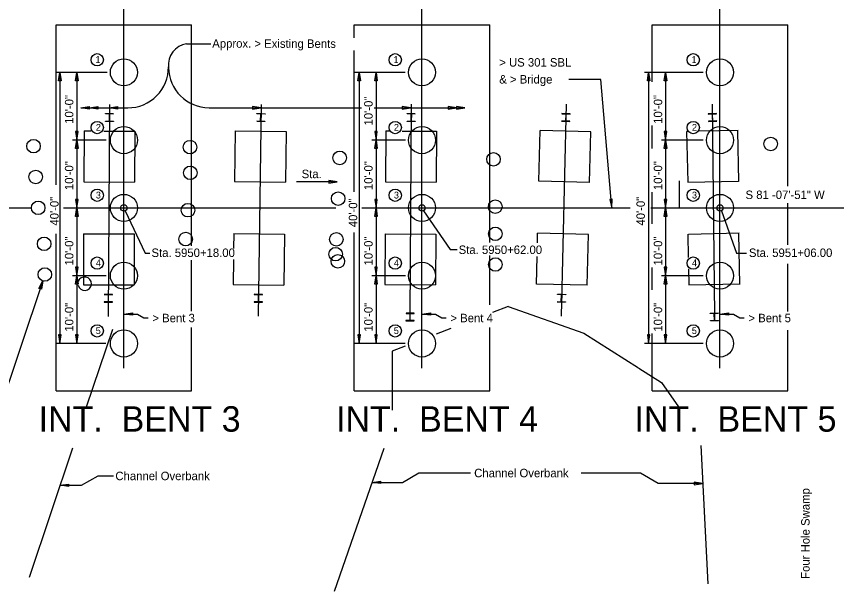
# Model space of a CAD drawing. Extents: x -10371 to -10009, y 1939 to 2167.
# Drawn here: x -10258.8 to -10137.7, y 2027.9 to 2112.7 of the extents above; entities that cross this region are included whole.
import ezdxf

# ---------------------------------------------------------------- set-up
doc = ezdxf.new("R2010")
doc.units = 0
for name, color, linetype in [('BR_AUTO DIMENSION', 7, 'Continuous'), ('BR_CENTER LINES', 7, 'Continuous'), ('BR_CONCRETE', 7, 'Continuous'), ('BR_STRUCTURAL STEEL', 7, 'Continuous'), ('BR_TABLE LINES', 7, 'Continuous'), ('BR_TEXT', 7, 'Continuous'), ('Default', 7, 'Continuous')]:
    doc.layers.add(name, color=color, linetype=linetype)

msp = doc.modelspace()

# ---------------------------------------------------------------- linework, layer by layer
at = {"layer": 'BR_AUTO DIMENSION'}
for p, q in [((-10233.68, 2108.7), (-10230.06, 2108.7)), ((-10245.4, 2104.49), (-10252.99, 2104.49)), ((-10252.37, 2104.49), (-10252.37, 2064.49)), ((-10249.87, 2104.49), (-10249.87, 2064.49)), ((-10249.69, 2104.49), (-10249.69, 2104.49)), ((-10201.4, 2104.49), (-10208.81, 2104.49)), ((-10208.19, 2104.49), (-10208.19, 2064.49)), ((-10205.69, 2104.49), (-10205.69, 2104.49)), ((-10205.69, 2104.49), (-10205.69, 2064.49)), ((-10157.4, 2104.49), (-10166.06, 2104.49)), ((-10165.44, 2104.49), (-10165.44, 2064.49)), ((-10162.94, 2104.49), (-10162.94, 2104.49)), ((-10162.94, 2104.49), (-10162.94, 2064.49)), ((-10172.48, 2103.43), (-10177.22, 2103.43)), ((-10170.87, 2084.49), (-10172.48, 2103.43)), ((-10249.27, 2099.26), (-10242.33, 2099.26)), ((-10230.33, 2099.26), (-10207.82, 2099.26)), ((-10205.95, 2099.26), (-10192.56, 2099.26)), ((-10245.54, 2094.49), (-10250.49, 2094.49)), ((-10201.36, 2094.49), (-10206.31, 2094.49)), ((-10157.4, 2094.49), (-10163.56, 2094.49)), ((-10211.43, 2088.32), (-10217.41, 2088.32)), ((-10242.7, 2084.07), (-10239.75, 2077.83)), ((-10198.7, 2084.07), (-10194.72, 2078.36)), ((-10154.7, 2084.07), (-10152.48, 2077.83)), ((-10239.75, 2077.83), (-10239.1, 2077.83)), ((-10194.72, 2078.36), (-10193.7, 2078.36)), ((-10152.48, 2077.83), (-10151.02, 2077.83)), ((-10245.54, 2074.49), (-10250.49, 2074.49)), ((-10201.36, 2074.49), (-10206.31, 2074.49)), ((-10157.4, 2074.49), (-10163.56, 2074.49)), ((-10254.89, 2073.72), (-10265.12, 2043.24)), ((-10242.91, 2068.83), (-10240.91, 2068.83)), ((-10240.91, 2068.83), (-10239.97, 2068.29)), ((-10239.97, 2068.29), (-10239.32, 2068.29)), ((-10198.91, 2068.83), (-10196.91, 2068.83)), ((-10196.91, 2068.83), (-10195.97, 2068.29)), ((-10195.97, 2068.29), (-10195.32, 2068.29)), ((-10154.91, 2068.83), (-10152.91, 2068.83)), ((-10152.91, 2068.83), (-10151.97, 2068.29)), ((-10151.97, 2068.29), (-10151.32, 2068.29)), ((-10245.58, 2064.49), (-10252.99, 2064.49)), ((-10249.87, 2064.49), (-10249.87, 2064.49)), ((-10201.4, 2064.49), (-10208.81, 2064.49)), ((-10205.69, 2064.49), (-10205.69, 2064.49)), ((-10157.4, 2064.49), (-10166.06, 2064.49)), ((-10162.94, 2064.49), (-10162.94, 2064.49)), ((-10201.76, 2043.99), (-10199.35, 2045.39)), ((-10199.35, 2045.39), (-10191.72, 2045.39)), ((-10166.66, 2045.35), (-10175.41, 2045.35)), ((-10164.05, 2043.84), (-10166.66, 2045.35)), ((-10249.15, 2043.56), (-10246.73, 2044.95)), ((-10246.73, 2044.95), (-10244.46, 2044.95)), ((-10206.27, 2043.99), (-10201.76, 2043.99)), ((-10252.34, 2043.56), (-10249.15, 2043.56)), ((-10157.46, 2043.84), (-10164.05, 2043.84))]:
    msp.add_line(p, q, dxfattribs=at)
for points in [[(-10252.56, 2103.24), (-10252.37, 2104.49), (-10252.18, 2103.24)], [(-10250.06, 2103.24), (-10249.87, 2104.49), (-10249.68, 2103.24)], [(-10208.38, 2103.24), (-10208.19, 2104.49), (-10208, 2103.24)], [(-10205.88, 2103.24), (-10205.69, 2104.49), (-10205.5, 2103.24)], [(-10165.63, 2103.24), (-10165.44, 2104.49), (-10165.25, 2103.24)], [(-10163.13, 2103.24), (-10162.94, 2104.49), (-10162.75, 2103.24)], [(-10248.02, 2099.08), (-10249.27, 2099.26), (-10248.02, 2099.45)], [(-10246.77, 2099.08), (-10248.02, 2099.26), (-10246.77, 2099.45)], [(-10243.86, 2099.08), (-10245.11, 2099.26), (-10243.86, 2099.45)], [(-10223.92, 2099.08), (-10222.67, 2099.26), (-10223.92, 2099.45)], [(-10201.81, 2099.08), (-10200.56, 2099.26), (-10201.81, 2099.45)], [(-10195.06, 2099.08), (-10193.81, 2099.26), (-10195.06, 2099.45)], [(-10193.81, 2099.08), (-10192.56, 2099.26), (-10193.81, 2099.45)], [(-10250.06, 2095.74), (-10249.87, 2094.49), (-10249.68, 2095.74)], [(-10205.88, 2095.74), (-10205.69, 2094.49), (-10205.5, 2095.74)], [(-10163.13, 2095.74), (-10162.94, 2094.49), (-10162.75, 2095.74)], [(-10250.06, 2093.24), (-10249.87, 2094.49), (-10249.68, 2093.24)], [(-10205.88, 2093.24), (-10205.69, 2094.49), (-10205.5, 2093.24)], [(-10163.13, 2093.24), (-10162.94, 2094.49), (-10162.75, 2093.24)], [(-10212.68, 2088.13), (-10211.43, 2088.32), (-10212.68, 2088.51)], [(-10250.06, 2085.74), (-10249.87, 2084.49), (-10249.68, 2085.74)], [(-10205.88, 2085.74), (-10205.69, 2084.49), (-10205.5, 2085.74)], [(-10171.18, 2085.72), (-10170.87, 2084.49), (-10170.81, 2085.76)], [(-10163.13, 2085.74), (-10162.94, 2084.49), (-10162.75, 2085.74)], [(-10250.06, 2083.24), (-10249.87, 2084.49), (-10249.68, 2083.24)], [(-10205.88, 2083.24), (-10205.69, 2084.49), (-10205.5, 2083.24)], [(-10163.13, 2083.24), (-10162.94, 2084.49), (-10162.75, 2083.24)], [(-10250.06, 2075.74), (-10249.87, 2074.49), (-10249.68, 2075.74)], [(-10205.88, 2075.74), (-10205.69, 2074.49), (-10205.5, 2075.74)], [(-10163.13, 2075.74), (-10162.94, 2074.49), (-10162.75, 2075.74)], [(-10250.06, 2073.24), (-10249.87, 2074.49), (-10249.68, 2073.24)], [(-10205.88, 2073.24), (-10205.69, 2074.49), (-10205.5, 2073.24)], [(-10163.13, 2073.24), (-10162.94, 2074.49), (-10162.75, 2073.24)], [(-10255.46, 2072.59), (-10254.89, 2073.72), (-10255.1, 2072.48)], [(-10241.66, 2068.65), (-10242.91, 2068.83), (-10241.66, 2069.02)], [(-10197.66, 2068.65), (-10198.91, 2068.83), (-10197.66, 2069.02)], [(-10153.66, 2068.65), (-10154.91, 2068.83), (-10153.66, 2069.02)], [(-10252.56, 2065.74), (-10252.37, 2064.49), (-10252.18, 2065.74)], [(-10250.06, 2065.74), (-10249.87, 2064.49), (-10249.68, 2065.74)], [(-10208.38, 2065.74), (-10208.19, 2064.49), (-10208, 2065.74)], [(-10205.88, 2065.74), (-10205.69, 2064.49), (-10205.5, 2065.74)], [(-10165.63, 2065.74), (-10165.44, 2064.49), (-10165.25, 2065.74)], [(-10163.13, 2065.74), (-10162.94, 2064.49), (-10162.75, 2065.74)], [(-10205.02, 2043.81), (-10206.27, 2043.99), (-10205.02, 2044.18)], [(-10158.71, 2043.65), (-10157.46, 2043.84), (-10158.71, 2044.03)], [(-10251.09, 2043.37), (-10252.34, 2043.56), (-10251.09, 2043.74)]]:
    msp.add_lwpolyline(points, close=True, dxfattribs=at)
for centre in [(-10242.91, 2084.49), (-10198.91, 2084.49), (-10154.91, 2084.49)]:
    msp.add_circle(centre, 0.469, dxfattribs=at)
for centre, radius, start, end in [((-10233.19, 2105.58), 3.16, 98.8893, 186.288), ((-10242.33, 2105.26), 6, 270, 0.323), ((-10230.33, 2105.26), 6, 180.323, 270)]:
    msp.add_arc(centre, radius, start, end, dxfattribs=at)
at = {"layer": 'BR_CENTER LINES'}
for p, q in [((-10242.91, 2060.87), (-10242.91, 2124.66)), ((-10198.91, 2060.87), (-10198.91, 2124.66)), ((-10154.91, 2060.87), (-10154.91, 2124.66)), ((-10160.91, 2084.49), (-10160.91, 2088.49)), ((-10267.37, 2084.49), (-10256.58, 2084.49)), ((-10251.83, 2084.49), (-10211.63, 2084.49)), ((-10207.77, 2084.49), (-10168.15, 2084.49)), ((-10165.1, 2084.49), (-10123.98, 2084.49))]:
    msp.add_line(p, q, dxfattribs=at)
at = {"layer": 'BR_CONCRETE'}
for p, q in [((-10248.8, 2095.85), (-10248.85, 2088.35)), ((-10248.8, 2095.85), (-10247.8, 2095.84)), ((-10245.86, 2095.83), (-10241.3, 2095.8)), ((-10241.3, 2095.8), (-10241.35, 2088.3)), ((-10226.47, 2095.88), (-10226.57, 2088.38)), ((-10226.47, 2095.88), (-10218.97, 2095.77)), ((-10218.97, 2095.77), (-10219.07, 2088.27)), ((-10204.26, 2095.85), (-10204.31, 2088.35)), ((-10204.26, 2095.85), (-10203.77, 2095.85)), ((-10201.84, 2095.83), (-10196.76, 2095.8)), ((-10196.76, 2095.8), (-10196.81, 2088.3)), ((-10181.65, 2088.42), (-10181.46, 2095.91)), ((-10173.97, 2095.73), (-10181.46, 2095.91)), ((-10174.15, 2088.23), (-10173.97, 2095.73)), ((-10159.62, 2095.75), (-10159.79, 2095.74)), ((-10159.63, 2088.29), (-10159.79, 2095.74)), ((-10152.25, 2095.91), (-10157.93, 2095.79)), ((-10152.13, 2088.37), (-10152.3, 2095.87)), ((-10248.85, 2088.35), (-10241.35, 2088.3)), ((-10226.57, 2088.38), (-10219.07, 2088.27)), ((-10204.31, 2088.35), (-10196.81, 2088.3)), ((-10174.15, 2088.23), (-10181.65, 2088.42)), ((-10152.17, 2088.41), (-10159.67, 2088.24)), ((-10248.88, 2080.66), (-10241.38, 2080.66)), ((-10248.88, 2080.66), (-10248.88, 2073.16)), ((-10241.38, 2080.66), (-10241.38, 2073.16)), ((-10226.68, 2080.71), (-10226.71, 2078.5)), ((-10226.68, 2080.71), (-10219.18, 2080.61)), ((-10219.18, 2080.61), (-10219.28, 2073.11)), ((-10204.35, 2080.68), (-10204.4, 2073.18)), ((-10204.35, 2080.68), (-10196.85, 2080.64)), ((-10196.85, 2080.64), (-10196.9, 2073.14)), ((-10181.87, 2079.32), (-10181.83, 2080.75)), ((-10174.33, 2080.57), (-10181.83, 2080.75)), ((-10174.52, 2073.07), (-10174.33, 2080.57)), ((-10159.55, 2077.15), (-10159.63, 2080.62)), ((-10152.09, 2080.75), (-10159.58, 2080.58)), ((-10151.96, 2073.2), (-10152.13, 2080.7)), ((-10226.73, 2076.86), (-10226.78, 2073.21)), ((-10182.01, 2073.25), (-10181.91, 2077.32)), ((-10159.46, 2073.12), (-10159.51, 2075.48)), ((-10248.88, 2073.16), (-10241.38, 2073.16)), ((-10226.78, 2073.21), (-10219.28, 2073.11)), ((-10204.4, 2073.18), (-10196.9, 2073.14)), ((-10174.52, 2073.07), (-10182.01, 2073.25)), ((-10152, 2073.25), (-10159.5, 2073.08))]:
    msp.add_line(p, q, dxfattribs=at)
for centre in [(-10242.91, 2104.49), (-10198.91, 2104.49), (-10154.91, 2104.49), (-10242.91, 2094.49), (-10198.91, 2094.49), (-10154.91, 2094.49), (-10242.91, 2084.49), (-10198.91, 2084.49), (-10154.91, 2084.49), (-10242.91, 2074.49), (-10198.91, 2074.49), (-10154.91, 2074.49), (-10242.91, 2064.49), (-10198.91, 2064.49), (-10154.91, 2064.49)]:
    msp.add_circle(centre, 2, dxfattribs=at)
at = {"layer": 'BR_STRUCTURAL STEEL'}
for p, q in [((-10223.29, 2098.36), (-10223.29, 2098.4)), ((-10223.29, 2098.4), (-10222.08, 2098.38)), ((-10177.04, 2098.38), (-10178.26, 2098.4)), ((-10178.26, 2098.4), (-10178.26, 2098.36)), ((-10155.43, 2098.41), (-10156.65, 2098.38)), ((-10155.43, 2098.37), (-10155.43, 2098.41)), ((-10245.65, 2097.26), (-10245.65, 2097.31)), ((-10245.65, 2097.31), (-10245.12, 2097.3)), ((-10244.44, 2097.26), (-10245.65, 2097.26)), ((-10245.64, 2098.36), (-10245.64, 2098.4)), ((-10245.64, 2098.4), (-10244.43, 2098.39)), ((-10245.11, 2098.35), (-10245.64, 2098.36)), ((-10245.06, 2097.36), (-10245.06, 2098.29)), ((-10245.02, 2098.29), (-10245.02, 2097.36)), ((-10244.97, 2097.3), (-10244.44, 2097.3)), ((-10244.43, 2098.35), (-10244.96, 2098.35)), ((-10244.44, 2097.3), (-10244.44, 2097.26)), ((-10244.43, 2098.39), (-10244.43, 2098.35)), ((-10223.31, 2097.27), (-10223.31, 2097.31)), ((-10223.31, 2097.31), (-10222.78, 2097.3)), ((-10222.09, 2097.25), (-10223.31, 2097.27)), ((-10222.76, 2098.35), (-10223.29, 2098.36)), ((-10222.72, 2097.36), (-10222.71, 2098.29)), ((-10222.66, 2098.29), (-10222.68, 2097.36)), ((-10222.62, 2097.3), (-10222.09, 2097.29)), ((-10222.08, 2098.34), (-10222.61, 2098.35)), ((-10222.09, 2097.29), (-10222.09, 2097.25)), ((-10222.08, 2098.38), (-10222.08, 2098.34)), ((-10201.11, 2097.26), (-10201.11, 2097.31)), ((-10201.11, 2097.31), (-10200.58, 2097.3)), ((-10199.89, 2097.26), (-10201.11, 2097.26)), ((-10201.1, 2098.36), (-10201.1, 2098.4)), ((-10201.1, 2098.4), (-10199.89, 2098.39)), ((-10200.57, 2098.35), (-10201.1, 2098.36)), ((-10200.52, 2097.36), (-10200.52, 2098.29)), ((-10200.47, 2098.29), (-10200.48, 2097.36)), ((-10199.89, 2098.35), (-10200.42, 2098.35)), ((-10200.42, 2097.3), (-10199.89, 2097.3)), ((-10199.89, 2098.39), (-10199.89, 2098.35)), ((-10199.89, 2097.3), (-10199.89, 2097.26)), ((-10177.76, 2097.3), (-10178.29, 2097.31)), ((-10178.29, 2097.31), (-10178.29, 2097.27)), ((-10178.29, 2097.27), (-10177.07, 2097.24)), ((-10178.26, 2098.36), (-10177.73, 2098.35)), ((-10177.68, 2098.29), (-10177.7, 2097.36)), ((-10177.66, 2097.35), (-10177.63, 2098.29)), ((-10177.07, 2097.28), (-10177.6, 2097.3)), ((-10177.58, 2098.35), (-10177.05, 2098.33)), ((-10177.07, 2097.24), (-10177.07, 2097.28)), ((-10177.05, 2098.33), (-10177.04, 2098.38)), ((-10156.65, 2098.38), (-10156.64, 2098.34)), ((-10156.64, 2098.34), (-10156.11, 2098.35)), ((-10156.09, 2097.3), (-10156.62, 2097.29)), ((-10156.62, 2097.29), (-10156.62, 2097.25)), ((-10156.62, 2097.25), (-10155.4, 2097.27)), ((-10156.06, 2098.3), (-10156.04, 2097.36)), ((-10155.99, 2097.36), (-10156.01, 2098.3)), ((-10155.96, 2098.35), (-10155.43, 2098.37)), ((-10155.41, 2097.32), (-10155.94, 2097.3)), ((-10155.4, 2097.27), (-10155.41, 2097.32)), ((-10245.3, 2070.64), (-10245.83, 2070.64)), ((-10245.83, 2070.64), (-10245.83, 2070.6)), ((-10245.83, 2070.6), (-10244.61, 2070.59)), ((-10244.6, 2071.72), (-10245.82, 2071.73)), ((-10245.82, 2071.73), (-10245.82, 2071.69)), ((-10245.82, 2071.69), (-10245.29, 2071.69)), ((-10245.23, 2071.63), (-10245.24, 2070.69)), ((-10245.2, 2070.69), (-10245.19, 2071.63)), ((-10244.61, 2070.63), (-10245.14, 2070.64)), ((-10245.13, 2071.69), (-10244.6, 2071.68)), ((-10244.61, 2070.59), (-10244.61, 2070.63)), ((-10244.6, 2071.68), (-10244.6, 2071.72)), ((-10223.15, 2070.64), (-10223.68, 2070.65)), ((-10223.68, 2070.65), (-10223.68, 2070.6)), ((-10223.68, 2070.6), (-10222.46, 2070.59)), ((-10222.45, 2071.72), (-10223.66, 2071.74)), ((-10223.66, 2071.74), (-10223.66, 2071.7)), ((-10223.66, 2071.7), (-10223.13, 2071.69)), ((-10223.08, 2071.63), (-10223.09, 2070.69)), ((-10223.05, 2070.69), (-10223.03, 2071.63)), ((-10222.46, 2070.63), (-10222.99, 2070.64)), ((-10222.98, 2071.69), (-10222.45, 2071.68)), ((-10222.46, 2070.59), (-10222.46, 2070.63)), ((-10222.45, 2071.68), (-10222.45, 2071.72)), ((-10178.93, 2070.61), (-10178.93, 2070.65)), ((-10178.93, 2070.65), (-10178.4, 2070.64)), ((-10177.72, 2070.58), (-10178.93, 2070.61)), ((-10178.91, 2071.7), (-10178.91, 2071.75)), ((-10178.91, 2071.75), (-10177.69, 2071.72)), ((-10178.38, 2071.69), (-10178.91, 2071.7)), ((-10178.35, 2070.7), (-10178.32, 2071.63)), ((-10178.28, 2071.63), (-10178.3, 2070.7)), ((-10178.25, 2070.64), (-10177.72, 2070.62)), ((-10177.69, 2071.67), (-10178.22, 2071.69)), ((-10177.72, 2070.62), (-10177.72, 2070.58)), ((-10177.69, 2071.72), (-10177.69, 2071.67)), ((-10200.05, 2068.96), (-10201.26, 2068.97)), ((-10201.26, 2068.97), (-10201.26, 2068.93)), ((-10201.26, 2068.93), (-10200.74, 2068.92)), ((-10200.68, 2068.87), (-10200.68, 2067.93)), ((-10200.64, 2067.93), (-10200.64, 2068.87)), ((-10200.58, 2068.92), (-10200.05, 2068.92)), ((-10200.05, 2068.92), (-10200.05, 2068.96)), ((-10156.35, 2068.95), (-10155.14, 2068.98)), ((-10156.35, 2068.91), (-10156.35, 2068.95)), ((-10155.82, 2068.92), (-10156.35, 2068.91)), ((-10155.74, 2067.93), (-10155.76, 2068.87)), ((-10155.72, 2068.87), (-10155.7, 2067.93)), ((-10155.13, 2068.94), (-10155.66, 2068.93)), ((-10155.14, 2068.98), (-10155.13, 2068.94)), ((-10200.74, 2067.87), (-10201.27, 2067.88)), ((-10201.27, 2067.88), (-10201.27, 2067.83)), ((-10201.27, 2067.83), (-10200.06, 2067.83)), ((-10200.06, 2067.87), (-10200.59, 2067.87)), ((-10200.06, 2067.83), (-10200.06, 2067.87)), ((-10156.33, 2067.86), (-10155.8, 2067.87)), ((-10156.32, 2067.82), (-10156.33, 2067.86)), ((-10155.11, 2067.85), (-10156.32, 2067.82)), ((-10155.64, 2067.88), (-10155.11, 2067.89)), ((-10155.11, 2067.89), (-10155.11, 2067.85))]:
    msp.add_line(p, q, dxfattribs=at)
for centre in [(-10147.42, 2093.93), (-10256.25, 2093.6), (-10233.15, 2093.46), (-10211.05, 2091.87), (-10188.35, 2091.66), (-10255.93, 2089.06), (-10233.11, 2089.67), (-10211.28, 2085.86), (-10255.56, 2084.5), (-10233.46, 2084.15), (-10188.09, 2084.67), (-10188.08, 2080.67), (-10233.79, 2079.89), (-10211.54, 2079.85), (-10254.69, 2079.19), (-10211.66, 2077.66), (-10211.32, 2076.61), (-10188.07, 2076.14), (-10254.58, 2074.67)]:
    msp.add_circle(centre, 1, dxfattribs=at)
for centre, radius, start, end in [((-10245.12, 2097.36), 0.0569, 269.6251, 359.6251), ((-10245.11, 2098.3), 0.0569, 359.6251, 89.6251), ((-10244.96, 2098.29), 0.0569, 89.6251, 179.6251), ((-10244.97, 2097.36), 0.0569, 179.6251, 269.6251), ((-10222.78, 2097.36), 0.0569, 269.2026, 359.2026), ((-10222.76, 2098.29), 0.0569, 359.2026, 89.2026), ((-10222.62, 2097.36), 0.0569, 179.2026, 269.2026), ((-10222.61, 2098.29), 0.0569, 89.2026, 179.2026), ((-10200.58, 2097.36), 0.0569, 269.6516, 359.6516), ((-10200.57, 2098.3), 0.0569, 359.6516, 89.6516), ((-10200.42, 2097.36), 0.0569, 179.6516, 269.6516), ((-10200.42, 2098.29), 0.0569, 89.6516, 179.6516), ((-10177.76, 2097.36), 0.0569, 268.6086, 358.6086), ((-10177.73, 2098.29), 0.0569, 358.6086, 88.6086), ((-10177.6, 2097.35), 0.0569, 178.6086, 268.6086), ((-10177.58, 2098.29), 0.0569, 88.6086, 178.6086), ((-10156.11, 2098.29), 0.0569, 1.2775, 91.2775), ((-10156.09, 2097.36), 0.0569, 271.2775, 1.2775), ((-10155.96, 2098.3), 0.0569, 91.2775, 181.2775), ((-10155.94, 2097.36), 0.0569, 181.2775, 271.2775), ((-10248.71, 2073.31), 1, 193.5328, 160.7088), ((-10245.3, 2070.69), 0.0569, 269.6251, 359.6251), ((-10245.29, 2071.63), 0.0569, 359.6251, 89.6251), ((-10245.14, 2070.69), 0.0569, 179.6251, 269.6251), ((-10245.13, 2071.63), 0.0569, 89.6251, 179.6251), ((-10223.15, 2070.69), 0.0569, 269.2026, 359.2026), ((-10223.13, 2071.63), 0.0569, 359.2026, 89.2026), ((-10222.99, 2070.69), 0.0569, 179.2026, 269.2026), ((-10222.98, 2071.63), 0.0569, 89.2026, 179.2026), ((-10178.4, 2070.7), 0.0569, 268.6086, 358.6086), ((-10178.38, 2071.63), 0.0569, 358.6086, 88.6086), ((-10178.25, 2070.69), 0.0569, 178.6086, 268.6086), ((-10178.22, 2071.63), 0.0569, 88.6086, 178.6086), ((-10200.74, 2068.87), 0.0569, 359.6516, 89.6516), ((-10200.58, 2068.86), 0.0569, 89.6516, 179.6516), ((-10155.82, 2068.87), 0.0569, 1.2775, 91.2775), ((-10155.66, 2068.87), 0.0569, 91.2775, 181.2775), ((-10200.74, 2067.93), 0.0569, 269.6516, 359.6516), ((-10200.59, 2067.93), 0.0569, 179.6516, 269.6516), ((-10155.8, 2067.93), 0.0569, 271.2775, 1.2775), ((-10155.64, 2067.93), 0.0569, 181.2775, 271.2775)]:
    msp.add_arc(centre, radius, start, end, dxfattribs=at)
at = {"layer": 'BR_TABLE LINES'}
for p, q in [((-10252.91, 2111.49), (-10232.91, 2111.49)), ((-10252.91, 2087.9), (-10252.91, 2111.49)), ((-10232.91, 2078.88), (-10232.91, 2111.49)), ((-10208.91, 2111.49), (-10188.91, 2111.49)), ((-10208.91, 2109.6), (-10208.91, 2111.49)), ((-10188.91, 2079.41), (-10188.91, 2111.49)), ((-10164.91, 2111.49), (-10144.91, 2111.49)), ((-10164.91, 2103.09), (-10164.91, 2111.49)), ((-10144.91, 2087.68), (-10144.91, 2111.49)), ((-10208.91, 2086.88), (-10208.91, 2107.71)), ((-10245.03, 2099.75), (-10245.23, 2068.49)), ((-10222.66, 2099.76), (-10223.1, 2068.51)), ((-10200.49, 2099.78), (-10200.68, 2068.52)), ((-10177.62, 2099.79), (-10178.38, 2068.54)), ((-10156.05, 2099.81), (-10155.7, 2068.56)), ((-10164.91, 2093.26), (-10164.91, 2096.64)), ((-10164.91, 2082.16), (-10164.91, 2086.81)), ((-10144.91, 2079.06), (-10144.91, 2085.21)), ((-10252.91, 2057.49), (-10252.91, 2080.66)), ((-10208.91, 2057.49), (-10208.91, 2080.85)), ((-10232.91, 2069.27), (-10232.91, 2076.78)), ((-10188.91, 2070.17), (-10188.91, 2077.46)), ((-10164.91, 2072.39), (-10164.91, 2075.71)), ((-10144.91, 2069.23), (-10144.91, 2076.22)), ((-10232.91, 2057.49), (-10232.91, 2066.86)), ((-10188.91, 2057.49), (-10188.91, 2066.86)), ((-10164.91, 2057.49), (-10164.91, 2065.94)), ((-10144.91, 2057.49), (-10144.91, 2066.45)), ((-10252.91, 2057.49), (-10232.91, 2057.49)), ((-10208.91, 2057.49), (-10188.91, 2057.49)), ((-10164.91, 2057.49), (-10144.91, 2057.49))]:
    msp.add_line(p, q, dxfattribs=at)
at = {"layer": 'BR_TEXT'}
for p, q in [((-10244.59, 2066.57), (-10248.47, 2055.07)), ((-10250.49, 2049.06), (-10256.91, 2029.98))]:
    msp.add_line(p, q, dxfattribs=at)
for points in [[(-10186.2, 2069.95), (-10188.5, 2069.06)], [(-10186.2, 2069.95), (-10175.01, 2065.99), (-10166.96, 2060.88)], [(-10194.66, 2066.7), (-10196.83, 2065.86)], [(-10201.38, 2064.11), (-10203.33, 2063.36), (-10203.3, 2054.67)], [(-10166.91, 2060.85), (-10163.54, 2058.72)], [(-10163.54, 2058.72), (-10161.04, 2055.12)], [(-10204.53, 2049), (-10211.87, 2027.88)], [(-10157.75, 2049.44), (-10156.72, 2029.01)]]:
    msp.add_lwpolyline(points, dxfattribs=at)
for centre in [(-10246.85, 2106.35), (-10202.85, 2106.35), (-10158.85, 2106.35), (-10246.85, 2096.35), (-10202.85, 2096.35), (-10158.85, 2096.35), (-10246.85, 2086.35), (-10202.85, 2086.35), (-10158.85, 2086.35), (-10246.85, 2076.35), (-10202.85, 2076.35), (-10158.85, 2076.35), (-10246.85, 2066.35), (-10202.85, 2066.35), (-10158.85, 2066.35)]:
    msp.add_circle(centre, 0.91, dxfattribs=at)
at = {"layer": 'Default'}
msp.add_circle((-10252.06, 2044.35), 0.001, dxfattribs=at)

# ---------------------------------------------------------------- texts
at = {"layer": 'BR_TEXT'}
for s, height, rotation, p in [('Approx. > Existing Bents', 1.25, 359.8933, (-10229.87, 2108.13)), ('10\'-0"', 1.25, 90, (-10250.37, 2096.89)), ('10\'-0"', 1.25, 90, (-10206.19, 2096.65)), ('10\'-0"', 1.25, 90, (-10163.44, 2096.89)), ('10\'-0"', 1.25, 90, (-10250.37, 2087.12)), ('10\'-0"', 1.25, 90, (-10206.19, 2087.12)), ('10\'-0"', 1.25, 90, (-10163.44, 2087.12)), ('Sta.', 1.25, 360, (-10216.67, 2088.88)), ('40\'-0"', 1.25, 90, (-10252.55, 2081.88)), ('40\'-0"', 1.25, 90, (-10208.46, 2081.64)), ('40\'-0"', 1.25, 90, (-10166, 2081.88)), ('10\'-0"', 1.25, 90, (-10250.37, 2076)), ('10\'-0"', 1.25, 90, (-10206.19, 2076)), ('10\'-0"', 1.25, 90, (-10163.44, 2076)), ('10\'-0"', 1.25, 90, (-10250.37, 2066.23)), ('10\'-0"', 1.25, 90, (-10206.19, 2066.23)), ('10\'-0"', 1.25, 90, (-10163.44, 2066.23)), ('INT.  BENT 3', 3.75, 360, (-10255.5, 2051.48)), ('INT.  BENT 4', 3.75, 360, (-10211.59, 2051.48)), ('INT.  BENT 5', 3.75, 360, (-10167.53, 2051.48)), ('Four Hole Swamp', 1.25, 90, (-10141.68, 2029.76))]:
    msp.add_text(s, height=height, rotation=rotation, dxfattribs=at).set_placement(p)
for s, height, p in [('1', 1, (-10247.11, 2105.88)), ('1', 1, (-10203.11, 2105.88)), ('1', 1, (-10159.11, 2105.88)), ('> US 301 SBL ', 1.25, (-10187.5, 2105.34)), ('& > Bridge ', 1.25, (-10187.5, 2102.84)), ('2', 1, (-10247.05, 2095.88)), ('2', 1, (-10203.05, 2095.88)), ('2', 1, (-10159.05, 2095.88)), ('3', 1, (-10247.05, 2085.88)), ('3', 1, (-10203.05, 2085.88)), ('3', 1, (-10159.05, 2085.88)), ('S 81 -07\'-51" W', 1.25, (-10151.14, 2085.8)), ('Sta. 5950+18.00', 1.25, (-10238.84, 2077.25)), ('Sta. 5950+62.00', 1.25, (-10193.49, 2077.69)), ('Sta. 5951+06.00', 1.25, (-10150.64, 2077.25)), ('4', 1, (-10247.05, 2075.88)), ('4', 1, (-10203.05, 2075.88)), ('4', 1, (-10159.05, 2075.88)), ('> Bent 3', 1.25, (-10238.71, 2067.62)), ('> Bent 4', 1.25, (-10194.71, 2067.62)), ('> Bent 5', 1.25, (-10150.71, 2067.62)), ('5', 1, (-10247.07, 2065.88)), ('5', 1, (-10203.07, 2065.88)), ('5', 1, (-10159.07, 2065.88)), ('Channel Overbank', 1.25, (-10244.17, 2044.32)), ('Channel Overbank', 1.25, (-10191.2, 2044.75))]:
    msp.add_text(s, height=height, dxfattribs=at).set_placement(p)

doc.saveas('drawing.dxf')
